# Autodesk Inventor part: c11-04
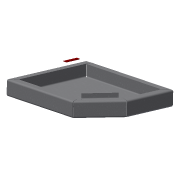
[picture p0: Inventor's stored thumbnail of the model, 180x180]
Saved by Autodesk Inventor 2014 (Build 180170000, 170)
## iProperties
Created: 2011-01
Part Number: c11-04
Material: Steel, Mild
Document SubType Name: Sheet Metal
Designer: Thom Tremblay
Density: 7.86 g/cm^3
Sheet Metal Rule: Steel - 16ga
Appearance: Galvanized
Author: Thom Tremblay
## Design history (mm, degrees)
node "Face1"
  sketch "Sketch1"
    geometry: L1 (0, 0)-(240, 0); L2 (240, 0)-(240, 300); L3 (240, 300)-(0, 300); L4 (0, 300)-(0, 0); L5 (140, 300)-(240, 229.979)
    constraints: 10 end point, 2 parallel, 2 point on line, 1 horizontal, 1 perpendicular
    dimensions: "d0" = 240 distance of L3.end L2.end; "d1" = 300 distance of L2.end L1.end; "d2" = 35 deg angle of L3 L5; "d3" = 100 distance from line of L2 L5.start
node "Flange1"
node "Flange2"
workplane "Work Plane1"
node "Flange3"
node "Face2"
  sketch "Sketch4"
    geometry: L1 (0, 15.428)-(214.889, 15.428) reference; L2 (25, 5.428)-(65, 5.428); L3 (65, 5.428)-(65, -4.572); L4 (65, -4.572)-(25, -4.572); L5 (25, -4.572)-(25, 5.428); 1 further point
    constraints: 8 end point, 2 parallel, 1 horizontal, 1 perpendicular
    dimensions: "d27" = 25 distance from line of L5 L1.start; "d28" = 10 distance of L4.end L2.start; "d29" = 40 distance of L3.end L4.end; "d50" = 10 distance between parallel lines of L1 L2
sketch "Sketch5"
  geometry: L1 (0, 15.428)-(214.889, 15.428) reference; L2 (160, 5.428)-(200, 5.428); L3 (200, 5.428)-(200, -18.572); L4 (160, -4.572)-(160, 5.428); L5 (200, -18.572)-(175, -18.572); L6 (175, -18.572)-(175, -12.572); L7 (175, -12.572)-(187, -12.572); L8 (187, -4.572)-(160, -4.572); A1 r 4 centre (187, -8.572) between (187, -12.572) and (187, -4.572); 1 further point
  constraints: 14 end point, 3 parallel, 3 perpendicular, 2 point on circle, 2 tangent, 1 centre point, 1 horizontal
  dimensions: "d30" = 10 distance of L4.start L2.start (= d28); "d32" = 160 distance from line of L1.start L4; "d51" = 10 distance between parallel lines of L1 L2; "d52" = 40 distance between parallel lines of L3 L4; "d53" = 25 distance of L3.end L5.end; "d54" = 12 distance from line of A1.centre L6; "d55" = 4 radius of A1; "d56" = 24 distance of L2.end L3.end
body "Solid1"
face "Plate1" dims "Thickness" = 1.524 (derived)
sketch "Sketch2"
  geometry: L1 through (-150, 0) direction (1, 0); L2 through (0, 20) direction (0, 1); L3 (0, 40)-(-300, 40); L4 (-300, 40)-(-300, 0)
  constraints: 6 end point, 1 horizontal, 1 perpendicular, 1 vertical
face "Plate2" dims "d5" = 1.524 (= BendReliefWidth), "d6" = 0.762 (= BendReliefDepth), "d7" = 3.048 (= MinimumRemnant), "d8" = 3.048 (= BendRadius), "d9" = 40, "d10" = 90 deg, "d11" = 3.048 (= BendRadius), "d12" = 6.096 (= CornerReliefSize), "d13" = 0.762 (= GapSize), "d14" = 3.048 (= JacobiRadiusSize), "SeamGap" = 0.01, "Thickness" = 1.524 (derived)
bend "Bend1" dims "d5" = 1.524 (= BendReliefWidth), "d6" = 0.762 (= BendReliefDepth), "d7" = 3.048 (= MinimumRemnant), "d8" = 3.048 (= BendRadius), "d9" = 40, "d10" = 90 deg, "d11" = 3.048 (= BendRadius), "SeamGap" = 0.01, "Thickness" = 1.524 (derived)
feature "Corner1" dims "d9" = 40, "d10" = 90 deg, "d12" = 6.096 (= CornerReliefSize), "d13" = 0.762 (= GapSize), "d14" = 3.048 (= JacobiRadiusSize)
sketch "Sketch3"
  geometry: L1 through (0, 147.937) direction (0, -1); L2 through (10, 0) direction (1, -4.12e-50); L3 (20, 0)-(20, 295.874); L4 (20, 295.874)-(0, 295.874)
  constraints: 6 end point, 1 horizontal, 1 perpendicular, 1 vertical
face "Plate3" dims "d15" = 1.524 (= BendReliefWidth), "d16" = 0.762 (= BendReliefDepth), "d17" = 3.048 (= MinimumRemnant), "d18" = 3.048 (= BendRadius), "d19" = 20, "d20" = 90 deg, "d21" = 3.048 (= BendRadius), "d22" = 6.096 (= CornerReliefSize), "d23" = 0.762 (= GapSize), "d24" = 3.048 (= JacobiRadiusSize), "d25" = 10, "SeamGap" = 0.01, "Thickness" = 1.524 (derived)
bend "Bend2" dims "d15" = 1.524 (= BendReliefWidth), "d16" = 0.762 (= BendReliefDepth), "d17" = 3.048 (= MinimumRemnant), "d18" = 3.048 (= BendRadius), "d19" = 20, "d20" = 90 deg, "d21" = 3.048 (= BendRadius), "SeamGap" = 0.01, "Thickness" = 1.524 (derived)
feature "Corner2" dims "d19" = 20, "d20" = 90 deg, "d22" = 6.096 (= CornerReliefSize), "d23" = 0.762 (= GapSize), "d24" = 3.048 (= JacobiRadiusSize)
face "Plate4" dims "d33" = 3.048 (= BendRadius), "d34" = 1.524 (= BendReliefWidth), "d36" = 3.048 (= MinimumRemnant), "Thickness" = 1.524 (derived)
bend "Bend3" dims "d33" = 3.048 (= BendRadius), "d34" = 1.524 (= BendReliefWidth), "d35" = 0.762 (= BendReliefDepth), "d36" = 3.048 (= MinimumRemnant), "d37" = 3.048 (= BendRadius), "SeamGap" = 0.01, "Thickness" = 1.524 (derived)
sketch "Sketch6"
  geometry: L1 (-94.531, 0)-(-10, 0); L2 (-10, 0)-(-10, 15); L3 (-10, 15)-(-94.531, 15); L4 (-94.531, 15)-(-94.531, 0)
  constraints: 8 end point
face "Plate5" dims "d38" = 1.524 (= BendReliefWidth), "d39" = 0.762 (= BendReliefDepth), "d40" = 3.048 (= MinimumRemnant), "d41" = 3.048 (= BendRadius), "d42" = 10, "d43" = 10, "d44" = 15, "d45" = 90 deg, "d46" = 3.048 (= BendRadius), "d47" = 6.096 (= CornerReliefSize), "d48" = 0.762 (= GapSize), "d49" = 3.048 (= JacobiRadiusSize), "SeamGap" = 0.01, "Thickness" = 1.524 (derived)
bend "Bend4" dims "d38" = 1.524 (= BendReliefWidth), "d39" = 0.762 (= BendReliefDepth), "d40" = 3.048 (= MinimumRemnant), "d41" = 3.048 (= BendRadius), "d44" = 15, "d45" = 90 deg, "d46" = 3.048 (= BendRadius), "SeamGap" = 0.01, "Thickness" = 1.524 (derived)
feature "Corner3" dims "d44" = 15, "d45" = 90 deg, "d47" = 6.096 (= CornerReliefSize), "d48" = 0.762 (= GapSize), "d49" = 3.048 (= JacobiRadiusSize)
other parameters: "BendRadius" = 3.048 (= 2 x Thickness), "BendReliefWidth" = 1.524 (= Thickness), "BendReliefDepth" = 0.762 (= 0.5 x Thickness), "CornerReliefSize" = 6.096 (= 4 x Thickness), "MinimumRemnant" = 3.048 (= 2 x Thickness), "TransitionRadius" = 3.048 (= BendRadius), "JacobiRadiusSize" = 3.048 (= BendRadius), "GapSize" = 0.762 (= 0.5 x Thickness), "d4" = 3.048 (= BendRadius)
